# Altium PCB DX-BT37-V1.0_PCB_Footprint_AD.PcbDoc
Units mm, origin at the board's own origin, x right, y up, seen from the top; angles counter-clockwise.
Board outline 152.4 x 101.6 mm, 2 copper layers (Top Layer, Bottom Layer); 1 components, 15 nets, 16 pads, 0 vias.
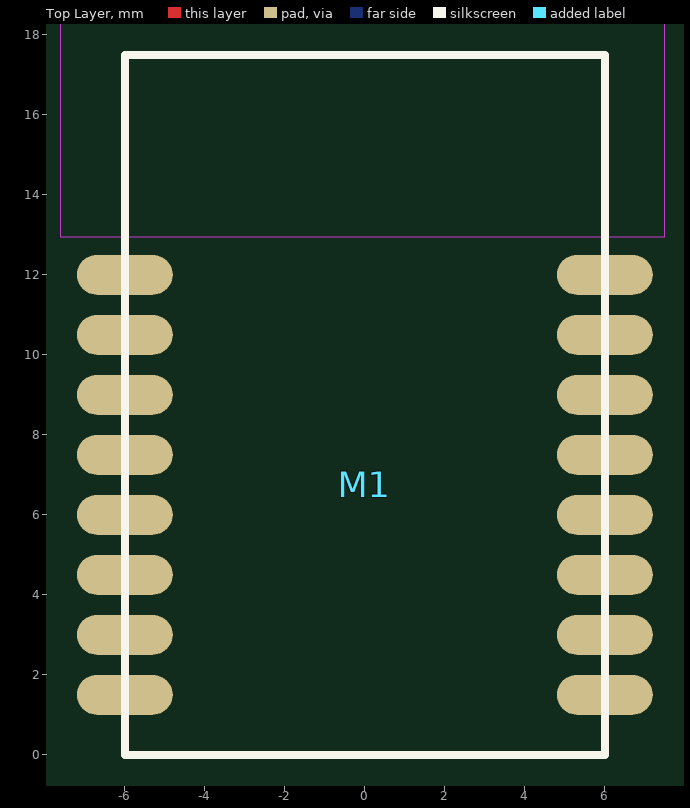
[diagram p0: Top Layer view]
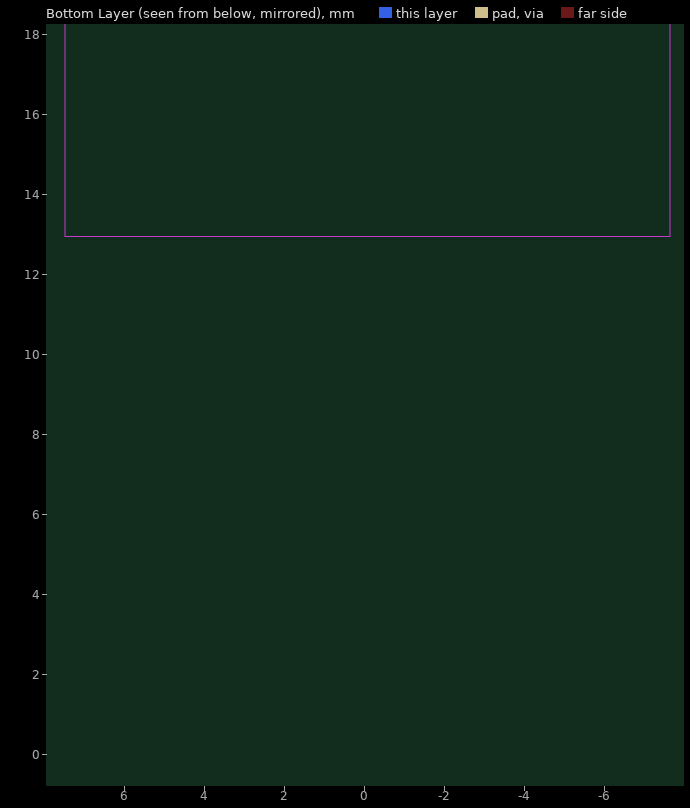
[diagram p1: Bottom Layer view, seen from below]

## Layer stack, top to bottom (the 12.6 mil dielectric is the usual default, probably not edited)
Top Solder: solder mask 0.0102, Solder Resist, Dk 3.5
Top Layer: signal copper 0.0356
Dielectric 1: dielectric 0.32, FR-4, Dk 4.8
Bottom Layer: signal copper 0.0356
Bottom Solder: solder mask 0.0102, Solder Resist, Dk 3.5

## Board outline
-71.264,-39.508 81.136,-39.508 81.136,62.092 -71.264,62.092

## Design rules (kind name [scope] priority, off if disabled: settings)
Clearance [All] p1: gap=0.254 ignorepadtopadclearanceinfootprint=FALSE except(0: Arc-Hole Track-Hole SMDPad-Hole THPad-Hole Via-Hole Fill-Hole Poly-Hole Region-Hole Text-Hole)
PolygonConnect [All] p1: connectstyle=Relief reliefconductorwidth=0.254 reliefentries=4 polygonreliefangle="90 Angle" airgapwidth=0.254
RoutingVias [All] p1: holewidth=0.711 width=1.27 viastyle="Through Hole" minholewidth=0.711 minwidth=1.27 maxholewidth=0.711 maxwidth=1.27
SolderMaskExpansion [All] p1: expansion=0.102 istentingtop=FALSE
Width [All] p1: maxlimit=0.254 minlimit=0.254 preferedwidth=0.254
30 further rules are at their usual default settings.

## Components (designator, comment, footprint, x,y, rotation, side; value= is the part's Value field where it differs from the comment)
M1 "BT37" BT37-M 0,0 r0 top

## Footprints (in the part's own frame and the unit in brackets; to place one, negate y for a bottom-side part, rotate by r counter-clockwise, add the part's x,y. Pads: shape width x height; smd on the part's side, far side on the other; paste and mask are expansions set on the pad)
BT37-M [mm]
  oval 2.4x1 smd mask+0.102: 1(-6,12) 2(-6,10.5) 3(-6,9) 4(-6,7.5) 5(-6,6) 6(-6,4.5) 7(-6,3) 8(-6,1.5) 9(6,1.5) 10(6,3) 11(6,4.5) 12(6,6) 13(6,7.5) 14(6,9) 15(6,10.5) 16(6,12)
  Keep-Out Layer region: -7.62,12.954 7.493,12.954 7.493,18.669 -7.62,18.669
  silkscreen extent -6,0 6,17.5

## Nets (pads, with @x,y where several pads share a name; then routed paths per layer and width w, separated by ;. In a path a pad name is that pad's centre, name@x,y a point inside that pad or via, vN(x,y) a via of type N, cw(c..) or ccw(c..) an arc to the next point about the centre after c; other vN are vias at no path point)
ANT3: 
GND: 
P00/TX/D-: 
P01/RX/D+: 
P02: 
P03: 
P04: 
P05: 
P06: 
P07: 
P10: 
P11: 
P32: 
RSTN: 
VBAT: 
pads on no net: M1.1 M1.2 M1.3 M1.4 M1.5 M1.6 M1.7 M1.8 M1.9 M1.10 M1.11 M1.12 M1.13 M1.14 M1.15 M1.16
